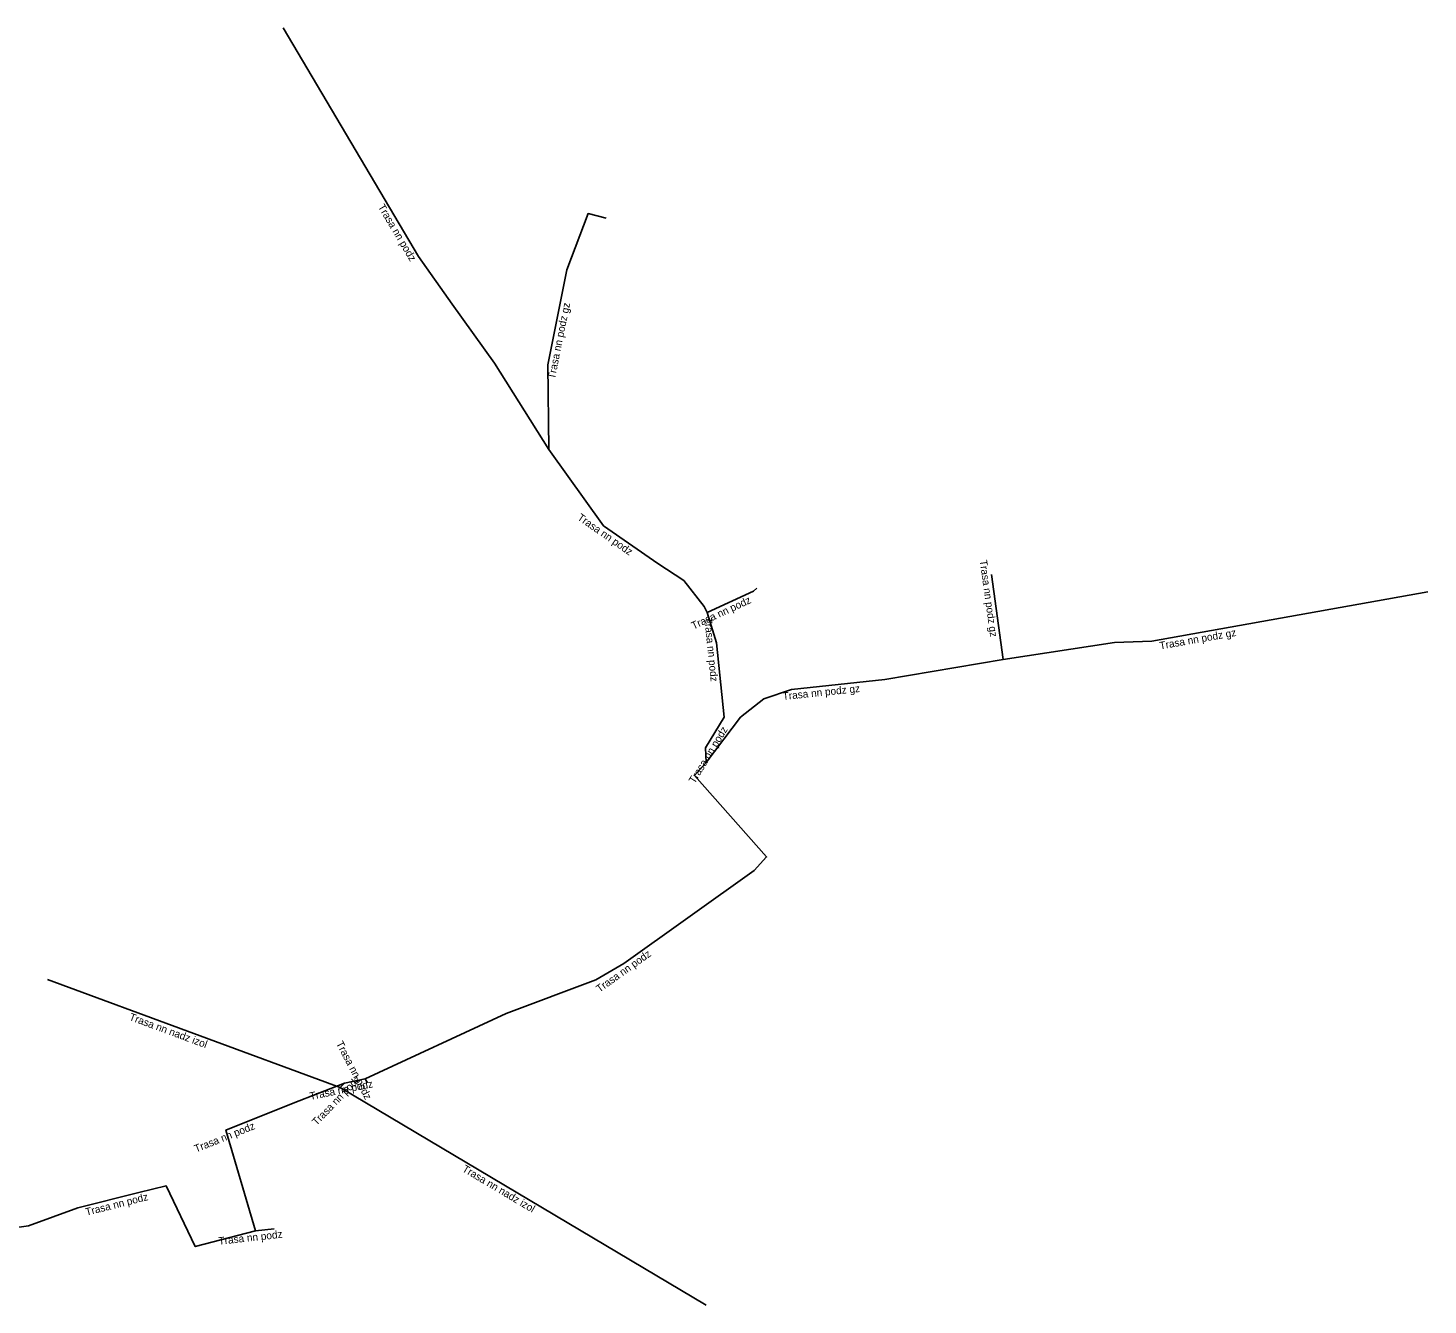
# Model space of a CAD drawing. Extents: x -677644 to -676951, y -1057278 to -1056718.
# Drawn here: x -677044.4 to -676951.3, y -1057082.8 to -1056997.9 of the extents above; entities that cross this region are included whole.
import ezdxf

# ---------------------------------------------------------------- set-up
doc = ezdxf.new("R2010")
doc.units = 0
doc.layers.add('Popiskový text - Ostatní atributy Trasy', color=7, linetype='Continuous')
doc.layers.add('Spojnice NN', color=7, linetype='Continuous')

msp = doc.modelspace()

# ---------------------------------------------------------------- linework, layer by layer
at = {"layer": 'Spojnice NN'}
for points in [[(-677027.42, -1056997.86), (-677018.44, -1057013.06), (-677016.19, -1057016.22), (-677013.38, -1057020.16), (-677009.77, -1057025.9)], [(-677005.95, -1057010.5), (-677007.16, -1057010.2), (-677008.56, -1057013.94), (-677009.83, -1057020.27), (-677009.77, -1057025.9)], [(-677009.77, -1057025.9), (-677006.13, -1057030.98), (-677002.52, -1057033.49), (-677000.78, -1057034.61), (-676999.44, -1057036.35), (-676999.24, -1057036.74)], [(-676979.55, -1057039.87), (-676980.34, -1057034.21)], [(-676999.24, -1057036.74), (-676996.15, -1057035.31), (-676995.94, -1057035.12)], [(-676979.55, -1057039.87), (-676972.16, -1057038.74), (-676969.67, -1057038.64), (-676951.31, -1057035.36)], [(-676999.24, -1057036.74), (-676998.61, -1057038.75), (-676998.11, -1057043.69)], [(-676999.31, -1057046.72), (-676997.02, -1057043.71), (-676995.47, -1057042.49), (-676993.64, -1057041.85), (-676987.43, -1057041.2), (-676979.55, -1057039.87)], [(-676998.11, -1057043.69), (-676999.36, -1057045.74), (-676999.31, -1057046.72)], [(-676999.31, -1057046.72), (-677000.08, -1057047.57), (-676995.29, -1057053), (-676996.12, -1057053.9), (-677004.78, -1057060.08), (-677006.64, -1057061.18), (-677012.61, -1057063.42), (-677021.97, -1057067.76)], [(-677023.63, -1057068.33), (-677043.105, -1057061.149)], [(-677021.97, -1057067.76), (-677023.35, -1057068.04)], [(-677021.97, -1057067.76), (-677021.83, -1057068.03)], [(-677029.27, -1057077.87), (-677031.24, -1057071.17), (-677026.76, -1057069.38), (-677023.35, -1057068.04)], [(-677023.35, -1057068.04), (-677023.63, -1057068.33)], [(-677023.63, -1057068.33), (-676999.3, -1057082.8)], [(-677029.27, -1057077.87), (-677033.28, -1057078.91), (-677035.21, -1057074.87), (-677037.02, -1057075.31), (-677041.08, -1057076.34), (-677044.37, -1057077.54), (-677048.36, -1057078.09)], [(-677028.02, -1057077.73), (-677029.27, -1057077.87)]]:
    msp.add_lwpolyline(points, dxfattribs=at)

# ---------------------------------------------------------------- texts
at = {"layer": 'Popiskový text - Ostatní atributy Trasy'}
for s, rotation, p in [('Trasa nn podz', 300.57415, (-677021.148, -1057009.753)), ('Trasa nn podz gz', 78.65526, (-677009.362, -1057021.242)), ('Trasa nn podz', 325.18946, (-677007.915, -1057030.53)), ('Trasa nn podz gz', 277.94578, (-676981.127, -1057033.273)), ('Trasa nn podz', 24.83391, (-677000.15, -1057037.878)), ('Trasa nn podz', 275.77949, (-676999.43, -1057037.106)), ('Trasa nn podz gz', 10.12899, (-676969.115, -1057039.201)), ('Trasa nn podz gz', 5.97538, (-676994.192, -1057042.561)), ('Trasa nn podz', 58.62699, (-677000.074, -1057048.16)), ('Trasa nn podz', 35.51264, (-677006.396, -1057062.032)), ('Trasa nn nadz izol', 339.7596, (-677037.711, -1057063.831)), ('Trasa nn podz', 297.40758, (-677023.926, -1057065.4)), ('Trasa nn podz', 11.46953, (-677025.615, -1057069.163)), ('Trasa nn podz', 46.00509, (-677025.208, -1057070.901)), ('Trasa nn podz', 21.77936, (-677033.223, -1057072.662)), ('Trasa nn nadz izol', 329.2584, (-677015.57, -1057073.88)), ('Trasa nn podz', 14.2353, (-677040.51, -1057076.866)), ('Trasa nn podz', 6.3905, (-677031.7, -1057078.797))]:
    msp.add_text(s, height=0.5, rotation=rotation, dxfattribs=at).set_placement(p)

doc.saveas('drawing.dxf')
